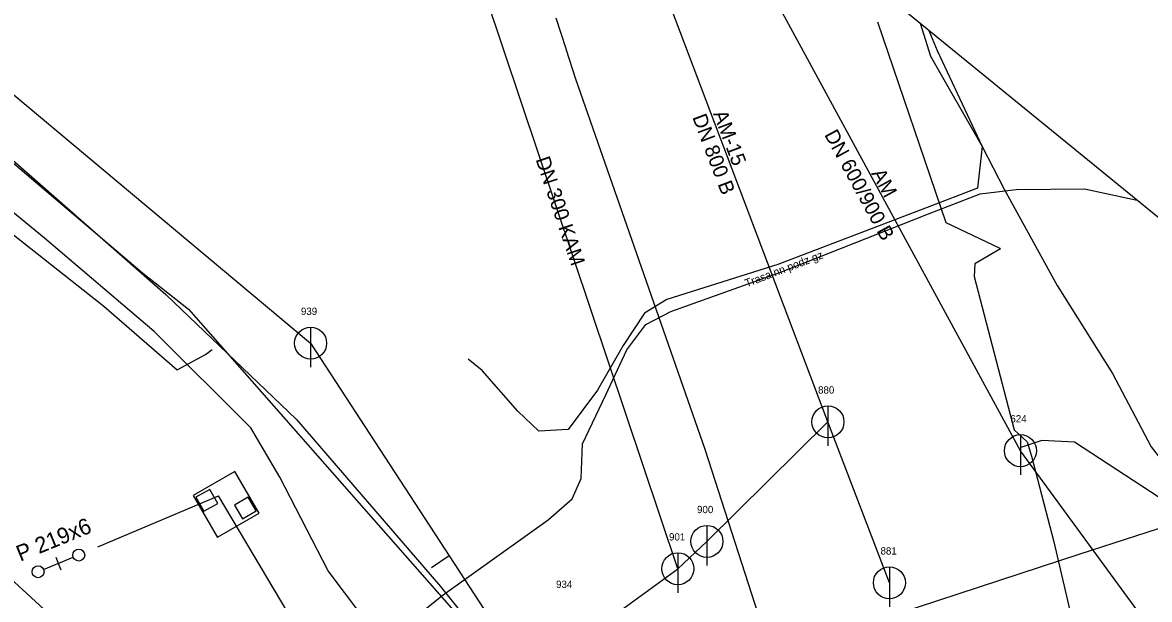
# Model space of a CAD drawing. Extents: x -492431 to -49223, y -1127123 to -112687.
# Drawn here: x -492244.4 to -492173.9, y -1126967.2 to -1126931.2 of the extents above; entities that cross this region are included whole.
import ezdxf

# ---------------------------------------------------------------- set-up
doc = ezdxf.new("R2010")
doc.units = 0
for name, color, linetype in [('Vrstva 1', 7, 'Continuous'), ('Vrstva 11', 7, 'Continuous'), ('Vrstva 12', 7, 'Continuous'), ('Vrstva 15', 7, 'Continuous'), ('Vrstva 17', 7, 'Continuous'), ('Vrstva 19', 7, 'Continuous'), ('Vrstva 20', 7, 'Continuous'), ('Vrstva 26', 7, 'Continuous'), ('Vrstva 45', 7, 'Continuous'), ('Vrstva 48', 7, 'Continuous'), ('Vrstva 49', 7, 'Continuous'), ('Vrstva 5', 7, 'Continuous'), ('Vrstva 6', 7, 'Continuous'), ('Vrstva 9', 7, 'Continuous')]:
    doc.layers.add(name, color=color, linetype=linetype)

msp = doc.modelspace()

# ---------------------------------------------------------------- linework, layer by layer
at = {"layer": 'Vrstva 1'}
for points in [[(-492341.24, -1127122.91), (-492133.025, -1126976.26), (-492272.695, -1126862.455), (-492313.78, -1126867.2)], [(-492160.583, -1126958.632), (-492171.348, -1126962.149), (-492178.287, -1126964.417), (-492197.297, -1126970.628), (-492217.66, -1126977.282)]]:
    msp.add_lwpolyline(points, dxfattribs=at)
at = {"layer": 'Vrstva 11'}
for points in [[(-492325.427, -1126870.004), (-492324.42, -1126871.11), (-492317.73, -1126878.62), (-492300.72, -1126895.4), (-492253.99, -1126932.28), (-492236.88, -1126946.83), (-492233.99, -1126949.1), (-492216.96, -1126968.47), (-492212.36, -1126974.41)], [(-492300.44, -1126895.31), (-492296.08, -1126899.46), (-492282.91, -1126910.11), (-492268.6, -1126921.1), (-492254.99, -1126931.66), (-492246.7, -1126938.29), (-492235.42, -1126948.18), (-492227.25, -1126955.99), (-492218.25, -1126966.43), (-492209.87, -1126976.88), (-492198.58, -1126993.76), (-492185.919, -1127013.514)]]:
    msp.add_lwpolyline(points, dxfattribs=at)
at = {"layer": 'Vrstva 12'}
for points in [[(-492225.27, -1126965.45), (-492228.3, -1126959.59), (-492230.1, -1126956.52), (-492236.14, -1126950.5), (-492242.99, -1126944.67), (-492248.49, -1126940.17), (-492254.17, -1126935.38), (-492261.23, -1126929.93), (-492271.91, -1126922.03), (-492280.13, -1126915.3), (-492289.67, -1126907.76), (-492299.8, -1126899.49), (-492301.86, -1126897.65)], [(-492208.85, -1126988.24), (-492213.18, -1126981.29), (-492218.27, -1126974.09), (-492223.16, -1126968.24), (-492225.27, -1126965.45)]]:
    msp.add_lwpolyline(points, dxfattribs=at)
at = {"layer": 'Vrstva 15'}
for p, q in [((-492273.445, -1126911.841), (-492226.365, -1126951.222)), ((-492182.01, -1126957.94), (-492203.056, -1126919.198)), ((-492194.038, -1126956.137), (-492206.808, -1126922.423)), ((-492203.417, -1126965.316), (-492216.6, -1126926.03)), ((-492226.365, -1126951.222), (-492185.781, -1127013.417)), ((-492256.219, -1126955.786), (-492237.176, -1126973.21)), ((-492201.6, -1126963.608), (-492194.038, -1126956.137)), ((-492190.199, -1126966.194), (-492194.038, -1126956.137)), ((-492156.473, -1126992.775), (-492182.01, -1126957.94)), ((-492203.417, -1126965.316), (-492201.6, -1126963.608)), ((-492218.816, -1126965.247), (-492217.709, -1126964.487)), ((-492214.677, -1126973.507), (-492203.417, -1126965.316))]:
    msp.add_line(p, q, dxfattribs=at)
at = {"layer": 'Vrstva 17'}
for p, q in [((-492226.365, -1126950.222), (-492226.365, -1126952.722)), ((-492194.038, -1126955.137), (-492194.038, -1126957.637)), ((-492182.01, -1126956.94), (-492182.01, -1126959.44)), ((-492201.6, -1126962.608), (-492201.6, -1126965.108)), ((-492203.417, -1126964.316), (-492203.417, -1126966.816)), ((-492190.199, -1126965.194), (-492190.199, -1126967.694))]:
    msp.add_line(p, q, dxfattribs=at)
for centre in [(-492226.365, -1126951.222), (-492194.038, -1126956.137), (-492182.01, -1126957.94), (-492201.6, -1126963.608), (-492203.417, -1126965.316), (-492190.199, -1126966.194)]:
    msp.add_circle(centre, 1, dxfattribs=at)
at = {"layer": 'Vrstva 20'}
msp.add_lwpolyline([(-492156.18, -1126967.55), (-492159.7, -1126969.78), (-492178.64, -1126957.41), (-492180.67, -1126957.3), (-492181.989, -1126957.751)], dxfattribs=at)
at = {"layer": 'Vrstva 26'}
for p, q in [((-492211.04, -1126930.89), (-492210.42, -1126932.81)), ((-492190.95, -1126931.14), (-492186.68, -1126943.68)), ((-492210.42, -1126932.81), (-492210.42, -1126932.84)), ((-492210.42, -1126932.84), (-492209.82, -1126934.7)), ((-492209.82, -1126934.7), (-492201.74, -1126957.84)), ((-492247.51, -1126942.43), (-492239.3, -1126948.92)), ((-492186.68, -1126943.68), (-492183.29, -1126945.28)), ((-492183.25, -1126945.32), (-492184.86, -1126946.26)), ((-492183.29, -1126945.28), (-492183.25, -1126945.32)), ((-492184.86, -1126946.26), (-492184.91, -1126947.06)), ((-492184.91, -1126947.06), (-492182.41, -1126956.64)), ((-492239.3, -1126948.92), (-492234.7, -1126952.88)), ((-492232.94, -1126951.93), (-492232.52, -1126951.61)), ((-492234.7, -1126952.88), (-492232.94, -1126951.93)), ((-492182.41, -1126956.64), (-492181.58, -1126957.39)), ((-492201.74, -1126957.84), (-492196.04, -1126975.47)), ((-492181.58, -1126957.39), (-492181.32, -1126958.28)), ((-492181.32, -1126958.28), (-492179.92, -1126963.64)), ((-492179.92, -1126963.64), (-492178.14, -1126971.21))]:
    msp.add_line(p, q, dxfattribs=at)
at = {"layer": 'Vrstva 45'}
for p, q in [((-492239.67, -1126963.95), (-492232.13, -1126960.76)), ((-492233.88, -1126961.5), (-492233.88, -1126961.5)), ((-492232.85, -1126961.07), (-492232.85, -1126961.07)), ((-492230.16, -1126964.07), (-492230.16, -1126964.07)), ((-492243.055, -1126965.362), (-492241.204, -1126964.604)), ((-492242.293, -1126964.585), (-492241.967, -1126965.381))]:
    msp.add_line(p, q, dxfattribs=at)
msp.add_lwpolyline([(-492225.16, -1126972.46), (-492232.13, -1126960.76)], dxfattribs=at)
for centre in [(-492240.857, -1126964.462), (-492243.402, -1126965.504)]:
    msp.add_circle(centre, 0.375, dxfattribs=at)
at = {"layer": 'Vrstva 48'}
for p, q in [((-492231.1, -1126959.24), (-492233.7, -1126960.75)), ((-492229.59, -1126961.85), (-492231.1, -1126959.24)), ((-492233.7, -1126960.75), (-492232.19, -1126963.36)), ((-492232.18, -1126963.35), (-492229.59, -1126961.85))]:
    msp.add_line(p, q, dxfattribs=at)
for points in [[(-492233.041, -1126961.721), (-492232.169, -1126961.231), (-492232.659, -1126960.36), (-492233.531, -1126960.849)], [(-492230.634, -1126962.203), (-492229.767, -1126961.705), (-492230.265, -1126960.838), (-492231.132, -1126961.336)]]:
    msp.add_lwpolyline(points, close=True, dxfattribs=at)
at = {"layer": 'Vrstva 5'}
for points in [[(-492188.28, -1126931.237), (-492187.634, -1126933.299), (-492184.403, -1126938.942), (-492184.693, -1126941.537), (-492187.84, -1126942.756), (-492197.164, -1126946.297), (-492204.099, -1126948.501), (-492205.5, -1126949.345), (-492206.842, -1126951.366), (-492208.436, -1126954.156), (-492210.262, -1126956.625), (-492212.111, -1126956.713), (-492213.423, -1126955.481), (-492215.643, -1126952.931), (-492216.526, -1126952.222)], [(-492187.724, -1126931.691), (-492187.216, -1126932.945), (-492184.403, -1126938.942), (-492183.024, -1126941.61), (-492179.718, -1126947.618), (-492176.254, -1126953.11), (-492173.843, -1126957.709), (-492168.669, -1126964.364), (-492165.183, -1126969.097), (-492161.989, -1126973.318), (-492158.94, -1126978.067), (-492155.573, -1126982.745), (-492151.438, -1126988.781), (-492151.192, -1126989.055)]]:
    msp.add_lwpolyline(points, dxfattribs=at)
at = {"layer": 'Vrstva 6'}
msp.add_lwpolyline([(-492263.25, -1126989.144), (-492261.731, -1126993.462), (-492260.081, -1126994.156), (-492257.598, -1126993.574), (-492254.965, -1126992.082), (-492246.089, -1126986.277), (-492240.252, -1126982.203), (-492231.099, -1126976.147), (-492223.494, -1126971.254), (-492218.08, -1126966.947), (-492211.53, -1126962.253), (-492210.012, -1126960.949), (-492209.47, -1126959.677), (-492209.378, -1126957.504), (-492207.928, -1126954.459), (-492206.61, -1126951.636), (-492205.409, -1126950.046), (-492203.864, -1126949.243), (-492197.049, -1126946.798), (-492187.754, -1126943.138), (-492184.528, -1126941.897), (-492182.28, -1126941.631), (-492177.997, -1126941.584), (-492174.72, -1126942.286)], dxfattribs=at)

# ---------------------------------------------------------------- texts
at = {"layer": 'Vrstva 19'}
for s, height, rotation, p in [('DN 800 B', 0.9099, 290.74541, (-492202.525, -1126937.1)), ('AM-15', 0.9099, 290.74541, (-492201.229, -1126936.871)), ('DN 600/900 B', 0.90989, 298.51205, (-492194.286, -1126938.188)), ('DN 300 KAM', 0.9099, 288.5501, (-492212.316, -1126939.734)), ('AM', 0.9099, 298.51205, (-492191.346, -1126940.612))]:
    msp.add_text(s, height=height, rotation=rotation, dxfattribs=at).set_placement(p)
for s, p in [('939', (-492226.972, -1126949.458)), ('880', (-492194.655, -1126954.373)), ('624', (-492182.638, -1126956.176)), ('900', (-492202.217, -1126961.844)), ('901', (-492203.969, -1126963.552)), ('881', (-492190.751, -1126964.43)), ('934', (-492211.027, -1126966.516))]:
    msp.add_text(s, height=0.4549, dxfattribs=at).set_placement(p)
at = {"layer": 'Vrstva 49'}
msp.add_text('K 108x5/ P 219x6', height=1, rotation=22.26951, dxfattribs=at).set_placement((-492249.738, -1126967.022))
at = {"layer": 'Vrstva 9'}
msp.add_text('Trasa nn podz gz', height=0.5, rotation=20.79541, dxfattribs=at).set_placement((-492199.119, -1126947.735))

doc.saveas('drawing.dxf')
